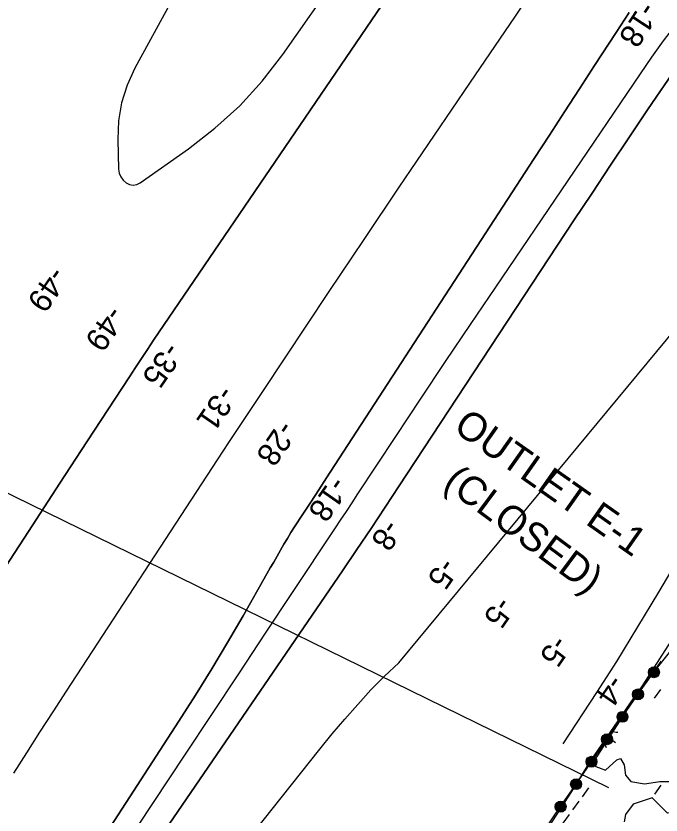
# Model space of a CAD drawing. Extents: x 3905714 to 3926767, y 183354 to 205755.
# Drawn here: x 3915542 to 3916488, y 190163 to 191335 of the extents above; entities that cross this region are included whole.
import ezdxf

# ---------------------------------------------------------------- set-up
doc = ezdxf.new("R2010")
doc.units = 0
for name, color, linetype in [('V-RIVR-EDGE', 7, 'Continuous'), ('V-RIVR-JETY', 7, 'Continuous'), ('V-RIVR-RANG', 7, 'Continuous'), ('V-RRAP-FSHR', 7, 'Continuous'), ('V-TOPO-DPTH', 7, 'Continuous'), ('V-TOPO-MAJR', 7, 'Continuous'), ('V-TOPO-MINR', 7, 'Continuous'), ('V-TOPO-SHOR', 7, 'Continuous'), ('V-UTIL-LINE', 7, 'Continuous'), ('V-WETL-SWMP', 7, 'Continuous')]:
    doc.layers.add(name, color=color, linetype=linetype)

msp = doc.modelspace()

# ---------------------------------------------------------------- linework, layer by layer
at = {"layer": 'V-RIVR-EDGE'}
msp.add_lwpolyline([(3917187.3, 191508.7), (3917014.4, 191257.7), (3916956.7, 191135), (3916863.8, 190988.1), (3916651.8, 190651.5), (3916385.9, 190236.8), (3916406.4, 190229.4), (3916423.1, 190244.3), (3916428.7, 190246.1), (3916434.2, 190236.8), (3916436.1, 190222), (3916443.5, 190212.7), (3916464, 190209), (3916486.3, 190212.7), (3916501.2, 190212.7), (3916512.3, 190207.1), (3916519.8, 190190.4), (3916521.6, 190179.2), (3916512.3, 190168.1), (3916497.5, 190166.2), (3916475.2, 190188.5), (3916447.3, 190179.2), (3916436.1, 190164.3), (3916434.2, 190153.2)], dxfattribs=at)
at = {"layer": 'V-RRAP-FSHR'}
for points in [[(3917284.6, 192007.4), (3917216.4, 191900.2), (3917136.8, 191773.1), (3917049.7, 191632.9), (3916990.5, 191517.4), (3916950.2, 191443.7), (3916837.1, 191198.3), (3916795.1, 191108.3), (3916723.3, 190937), (3916670, 190831.7), (3916645.3, 190765), (3916582.8, 190657.5), (3916484.4, 190490), (3916422.5, 190388.3), (3916393.5, 190343.3), (3916344.2, 190267.8)], [(3916317.9, 190142.8), (3916340.7, 190175.7), (3916363.4, 190208.6), (3916386.1, 190241.5), (3916408.8, 190274.5), (3916431.5, 190307.4), (3916454.2, 190340.3), (3916477.6, 190372.7), (3916502.3, 190404.2), (3916527.1, 190435.7)], [(3916475.1, 190365.9), (3916473.4, 190367.1), (3916471.2, 190369.5), (3916470.5, 190372), (3916470.9, 190375.2), (3916472.5, 190377.4), (3916475.1, 190379.5), (3916478, 190379.6), (3916480.3, 190379.4), (3916482.6, 190377.8), (3916484.1, 190375.7), (3916484.6, 190373.5), (3916484.6, 190371.2), (3916483.6, 190368.8), (3916481, 190366.5), (3916477.9, 190365.6), (3916475.5, 190365.9), (3916473.3, 190368.7), (3916471.7, 190371.2), (3916471.9, 190374), (3916473.3, 190376.9), (3916476, 190378.5), (3916479, 190378.5), (3916481.5, 190377.3), (3916483.3, 190374.8), (3916483.6, 190371.9), (3916482.1, 190368.8), (3916479.4, 190367.1), (3916476.6, 190366.8), (3916473.9, 190368.8), (3916472.8, 190371.3), (3916472.9, 190374.2), (3916474.4, 190376.5), (3916476.8, 190377.7), (3916479.5, 190377.5), (3916481.8, 190375.3), (3916482.6, 190372.6), (3916481, 190369.1), (3916478.4, 190367.8), (3916476.5, 190368), (3916474.5, 190370.2), (3916473.6, 190373), (3916474.5, 190375.3), (3916477.1, 190376.8), (3916479.4, 190376.3), (3916481.5, 190374), (3916481.3, 190371.6), (3916479.9, 190369.6), (3916478, 190368.6), (3916476.1, 190369.3), (3916475.1, 190371.1), (3916474.7, 190373.4), (3916475.9, 190375.1), (3916477.7, 190375.7), (3916479.7, 190374.9), (3916480.5, 190373.2), (3916480.2, 190371.4), (3916478.6, 190369.9), (3916477.3, 190369.9), (3916476.1, 190371.5), (3916475.8, 190373.4), (3916476.7, 190374.5), (3916478.2, 190374.5), (3916479.6, 190373.3), (3916479.3, 190371.7), (3916478.2, 190370.9), (3916476.9, 190371.8), (3916476.8, 190373.5), (3916478, 190373.6), (3916478.6, 190372.6), (3916478.2, 190371.9), (3916477.6, 190372.7)], [(3916452.1, 190333.3), (3916450.3, 190334.4), (3916448, 190336.7), (3916447.1, 190339.1), (3916447.4, 190342.3), (3916448.8, 190344.7), (3916451.3, 190346.9), (3916454.2, 190347.2), (3916456.4, 190347.2), (3916458.8, 190345.7), (3916460.4, 190343.7), (3916461.2, 190341.5), (3916461.2, 190339.3), (3916460.4, 190336.8), (3916457.9, 190334.3), (3916454.9, 190333.3), (3916452.5, 190333.4), (3916450.2, 190336), (3916448.4, 190338.4), (3916448.4, 190341.2), (3916449.6, 190344.2), (3916452.2, 190345.9), (3916455.2, 190346.2), (3916457.8, 190345.2), (3916459.7, 190342.8), (3916460.2, 190339.8), (3916458.9, 190336.6), (3916456.3, 190334.8), (3916453.6, 190334.3), (3916450.8, 190336.2), (3916449.5, 190338.6), (3916449.4, 190341.5), (3916450.8, 190343.9), (3916453.1, 190345.2), (3916455.8, 190345.2), (3916458.3, 190343.2), (3916459.2, 190340.5), (3916457.8, 190336.9), (3916455.3, 190335.4), (3916453.4, 190335.5), (3916451.2, 190337.6), (3916450.2, 190340.3), (3916451, 190342.7), (3916453.5, 190344.4), (3916455.8, 190344), (3916458, 190341.8), (3916458, 190339.4), (3916456.7, 190337.4), (3916454.8, 190336.3), (3916452.9, 190336.8), (3916451.8, 190338.5), (3916451.2, 190340.8), (3916452.3, 190342.5), (3916454.1, 190343.3), (3916456.2, 190342.6), (3916457.1, 190340.9), (3916456.9, 190339.2), (3916455.4, 190337.6), (3916454.1, 190337.4), (3916452.8, 190339), (3916452.4, 190340.8), (3916453.1, 190342), (3916454.7, 190342.1), (3916456.2, 190341), (3916456, 190339.4), (3916454.9, 190338.5), (3916453.5, 190339.4), (3916453.4, 190341), (3916454.5, 190341.2), (3916455.2, 190340.3), (3916454.9, 190339.5), (3916454.2, 190340.3)], [(3916429.4, 190300.4), (3916427.6, 190301.5), (3916425.3, 190303.8), (3916424.4, 190306.2), (3916424.7, 190309.4), (3916426.1, 190311.8), (3916428.6, 190314), (3916431.5, 190314.2), (3916433.7, 190314.2), (3916436.1, 190312.7), (3916437.7, 190310.8), (3916438.5, 190308.6), (3916438.5, 190306.3), (3916437.7, 190303.9), (3916435.2, 190301.4), (3916432.2, 190300.3), (3916429.8, 190300.5), (3916427.5, 190303.1), (3916425.7, 190305.5), (3916425.7, 190308.3), (3916426.9, 190311.2), (3916429.5, 190313), (3916432.5, 190313.2), (3916435.1, 190312.2), (3916437, 190309.8), (3916437.5, 190306.9), (3916436.2, 190303.7), (3916433.6, 190301.9), (3916430.9, 190301.4), (3916428.1, 190303.2), (3916426.8, 190305.7), (3916426.7, 190308.6), (3916428.1, 190311), (3916430.4, 190312.3), (3916433.1, 190312.2), (3916435.6, 190310.2), (3916436.5, 190307.6), (3916435.1, 190303.9), (3916432.6, 190302.5), (3916430.7, 190302.6), (3916428.5, 190304.7), (3916427.5, 190307.4), (3916428.3, 190309.7), (3916430.8, 190311.4), (3916433.1, 190311.1), (3916435.3, 190308.9), (3916435.2, 190306.5), (3916434, 190304.4), (3916432.1, 190303.3), (3916430.2, 190303.9), (3916429.1, 190305.6), (3916428.5, 190307.8), (3916429.6, 190309.6), (3916431.4, 190310.4), (3916433.5, 190309.7), (3916434.4, 190308), (3916434.2, 190306.2), (3916432.7, 190304.6), (3916431.3, 190304.5), (3916430.1, 190306), (3916429.6, 190307.9), (3916430.4, 190309.1), (3916432, 190309.2), (3916433.5, 190308.1), (3916433.3, 190306.5), (3916432.2, 190305.6), (3916430.8, 190306.4), (3916430.7, 190308.1), (3916431.8, 190308.3), (3916432.4, 190307.3), (3916432.1, 190306.5), (3916431.5, 190307.4)], [(3916406.7, 190267.5), (3916404.9, 190268.5), (3916402.6, 190270.8), (3916401.7, 190273.3), (3916402, 190276.5), (3916403.3, 190278.8), (3916405.9, 190281), (3916408.7, 190281.3), (3916411, 190281.3), (3916413.4, 190279.8), (3916415, 190277.9), (3916415.8, 190275.6), (3916415.8, 190273.4), (3916415, 190270.9), (3916412.5, 190268.5), (3916409.5, 190267.4), (3916407.1, 190267.5), (3916404.8, 190270.1), (3916403, 190272.5), (3916403, 190275.3), (3916404.2, 190278.3), (3916406.8, 190280.1), (3916409.8, 190280.3), (3916412.4, 190279.3), (3916414.3, 190276.9), (3916414.8, 190273.9), (3916413.5, 190270.8), (3916410.9, 190269), (3916408.2, 190268.5), (3916405.4, 190270.3), (3916404.1, 190272.8), (3916404, 190275.6), (3916405.3, 190278), (3916407.7, 190279.3), (3916410.4, 190279.3), (3916412.8, 190277.3), (3916413.8, 190274.6), (3916412.4, 190271), (3916409.9, 190269.6), (3916408, 190269.6), (3916405.8, 190271.8), (3916404.8, 190274.5), (3916405.6, 190276.8), (3916408.1, 190278.5), (3916410.4, 190278.1), (3916412.6, 190276), (3916412.5, 190273.6), (3916411.3, 190271.5), (3916409.4, 190270.4), (3916407.4, 190271), (3916406.4, 190272.7), (3916405.8, 190274.9), (3916406.9, 190276.7), (3916408.7, 190277.5), (3916410.8, 190276.8), (3916411.7, 190275.1), (3916411.5, 190273.3), (3916410, 190271.7), (3916408.6, 190271.6), (3916407.3, 190273.1), (3916406.9, 190275), (3916407.7, 190276.2), (3916409.3, 190276.3), (3916410.8, 190275.1), (3916410.6, 190273.5), (3916409.5, 190272.7), (3916408.1, 190273.5), (3916408, 190275.1), (3916409.1, 190275.4), (3916409.7, 190274.4), (3916409.4, 190273.6), (3916408.8, 190274.4)], [(3916384, 190234.5), (3916382.2, 190235.6), (3916379.9, 190237.9), (3916379, 190240.3), (3916379.2, 190243.5), (3916380.6, 190245.9), (3916383.1, 190248.1), (3916386, 190248.4), (3916388.3, 190248.4), (3916390.7, 190246.9), (3916392.3, 190244.9), (3916393.1, 190242.7), (3916393.1, 190240.5), (3916392.3, 190238), (3916389.8, 190235.5), (3916386.8, 190234.5), (3916384.4, 190234.6), (3916382.1, 190237.2), (3916380.3, 190239.6), (3916380.3, 190242.4), (3916381.5, 190245.4), (3916384.1, 190247.1), (3916387.1, 190247.4), (3916389.7, 190246.4), (3916391.6, 190244), (3916392.1, 190241), (3916390.8, 190237.8), (3916388.2, 190236), (3916385.5, 190235.6), (3916382.7, 190237.4), (3916381.4, 190239.9), (3916381.3, 190242.7), (3916382.6, 190245.1), (3916385, 190246.4), (3916387.7, 190246.4), (3916390.1, 190244.4), (3916391.1, 190241.7), (3916389.7, 190238.1), (3916387.2, 190236.6), (3916385.3, 190236.7), (3916383.1, 190238.8), (3916382.1, 190241.5), (3916382.9, 190243.9), (3916385.4, 190245.6), (3916387.7, 190245.2), (3916389.9, 190243.1), (3916389.8, 190240.6), (3916388.6, 190238.6), (3916386.7, 190237.5), (3916384.7, 190238), (3916383.7, 190239.8), (3916383.1, 190242), (3916384.2, 190243.8), (3916386, 190244.5), (3916388.1, 190243.8), (3916389, 190242.1), (3916388.8, 190240.4), (3916387.3, 190238.8), (3916385.9, 190238.6), (3916384.6, 190240.2), (3916384.2, 190242.1), (3916385, 190243.3), (3916386.6, 190243.3), (3916388.1, 190242.2), (3916387.8, 190240.6), (3916386.8, 190239.7), (3916385.4, 190240.6), (3916385.3, 190242.2), (3916386.4, 190242.4), (3916387, 190241.5), (3916386.7, 190240.7), (3916386.1, 190241.5)], [(3916361.3, 190201.6), (3916359.5, 190202.7), (3916357.2, 190205), (3916356.3, 190207.4), (3916356.5, 190210.6), (3916357.9, 190213), (3916360.4, 190215.2), (3916363.3, 190215.5), (3916365.6, 190215.4), (3916368, 190214), (3916369.6, 190212), (3916370.4, 190209.8), (3916370.4, 190207.5), (3916369.6, 190205.1), (3916367.1, 190202.6), (3916364.1, 190201.5), (3916361.7, 190201.7), (3916359.4, 190204.3), (3916357.6, 190206.7), (3916357.6, 190209.5), (3916358.8, 190212.5), (3916361.4, 190214.2), (3916364.4, 190214.4), (3916367, 190213.4), (3916368.9, 190211), (3916369.4, 190208.1), (3916368.1, 190204.9), (3916365.5, 190203.1), (3916362.8, 190202.6), (3916359.9, 190204.5), (3916358.7, 190206.9), (3916358.6, 190209.8), (3916359.9, 190212.2), (3916362.2, 190213.5), (3916365, 190213.4), (3916367.4, 190211.5), (3916368.3, 190208.8), (3916367, 190205.1), (3916364.5, 190203.7), (3916362.6, 190203.8), (3916360.4, 190205.9), (3916359.4, 190208.6), (3916360.1, 190210.9), (3916362.6, 190212.7), (3916365, 190212.3), (3916367.2, 190210.1), (3916367.1, 190207.7), (3916365.9, 190205.6), (3916364, 190204.5), (3916362, 190205.1), (3916361, 190206.8), (3916360.4, 190209), (3916361.5, 190210.8), (3916363.3, 190211.6), (3916365.3, 190210.9), (3916366.2, 190209.2), (3916366.1, 190207.5), (3916364.6, 190205.8), (3916363.2, 190205.7), (3916361.9, 190207.2), (3916361.5, 190209.1), (3916362.3, 190210.3), (3916363.9, 190210.4), (3916365.4, 190209.3), (3916365.1, 190207.7), (3916364.1, 190206.8), (3916362.7, 190207.6), (3916362.6, 190209.3), (3916363.7, 190209.5), (3916364.3, 190208.5), (3916364, 190207.8), (3916363.4, 190208.6)], [(3916338.6, 190168.7), (3916336.8, 190169.7), (3916334.5, 190172), (3916333.6, 190174.5), (3916333.8, 190177.7), (3916335.2, 190180.1), (3916337.7, 190182.2), (3916340.6, 190182.5), (3916342.9, 190182.5), (3916345.3, 190181), (3916346.9, 190179.1), (3916347.6, 190176.8), (3916347.7, 190174.6), (3916346.9, 190172.1), (3916344.4, 190169.7), (3916341.4, 190168.6), (3916339, 190168.7), (3916336.7, 190171.4), (3916334.9, 190173.7), (3916334.9, 190176.5), (3916336.1, 190179.5), (3916338.7, 190181.3), (3916341.7, 190181.5), (3916344.3, 190180.5), (3916346.2, 190178.1), (3916346.7, 190175.2), (3916345.4, 190172), (3916342.8, 190170.2), (3916340.1, 190169.7), (3916337.2, 190171.5), (3916336, 190174), (3916335.9, 190176.8), (3916337.2, 190179.2), (3916339.5, 190180.5), (3916342.3, 190180.5), (3916344.7, 190178.5), (3916345.6, 190175.8), (3916344.2, 190172.2), (3916341.8, 190170.8), (3916339.9, 190170.8), (3916337.7, 190173), (3916336.7, 190175.7), (3916337.4, 190178), (3916339.9, 190179.7), (3916342.3, 190179.4), (3916344.5, 190177.2), (3916344.4, 190174.8), (3916343.2, 190172.7), (3916341.3, 190171.6), (3916339.3, 190172.2), (3916338.3, 190173.9), (3916337.7, 190176.1), (3916338.8, 190177.9), (3916340.6, 190178.7), (3916342.6, 190178), (3916343.5, 190176.3), (3916343.4, 190174.5), (3916341.8, 190172.9), (3916340.5, 190172.8), (3916339.2, 190174.3), (3916338.8, 190176.2), (3916339.6, 190177.4), (3916341.2, 190177.5), (3916342.7, 190176.4), (3916342.4, 190174.7), (3916341.4, 190173.9), (3916340, 190174.7), (3916339.8, 190176.3), (3916341, 190176.6), (3916341.6, 190175.6), (3916341.3, 190174.8), (3916340.7, 190175.6)]]:
    msp.add_lwpolyline(points, dxfattribs=at)
for centre in [(3916477.6, 190372.7), (3916454.2, 190340.3), (3916431.5, 190307.4), (3916408.8, 190274.5), (3916386.1, 190241.5), (3916363.4, 190208.6), (3916340.7, 190175.7)]:
    msp.add_circle(centre, 8, dxfattribs=at)
at = {"layer": 'V-TOPO-DPTH'}
for points in [[(3916593.7, 192145.5), (3916213.5, 191553.1), (3916206.3, 191541.8), (3916199, 191530.5), (3916191.8, 191519.3), (3916184.5, 191508.1), (3916177.2, 191496.9), (3916169.8, 191485.7), (3916162.4, 191474.6), (3916154.9, 191463.5), (3916154.2, 191462.4), (3916146.3, 191450.8), (3916138.5, 191439.2), (3916130.6, 191427.6), (3916122.7, 191416), (3915744.1, 190859.5), (3915735.1, 190846.2), (3915726.2, 190832.9), (3915717.3, 190819.5), (3915708.5, 190806.1), (3915646.4, 190710.8), (3915606.5, 190649.8), (3915566.8, 190588.7), (3915527, 190527.5)], [(3916593.7, 192145.5), (3916213.5, 191553.1), (3916206.3, 191541.8), (3916199, 191530.5), (3916191.8, 191519.3), (3916184.5, 191508.1), (3916177.2, 191496.9), (3916169.8, 191485.7), (3916162.4, 191474.6), (3916154.9, 191463.5), (3916154.2, 191462.4), (3916146.3, 191450.8), (3916138.5, 191439.2), (3916130.6, 191427.6), (3916122.7, 191416), (3915744.1, 190859.5), (3915735.1, 190846.2), (3915726.2, 190832.9), (3915717.3, 190819.5), (3915708.5, 190806.1), (3915646.4, 190710.8), (3915606.5, 190649.8), (3915566.8, 190588.7), (3915527, 190527.5)], [(3917069.2, 191838.9), (3917052.8, 191814.6), (3917034.7, 191791.4), (3916628.8, 191406.9), (3916610.8, 191387.4), (3916593.6, 191367.1), (3916535.8, 191294.1), (3916529.6, 191286), (3916523.4, 191277.8), (3916517.5, 191269.6), (3916511.7, 191261.2), (3916468.4, 191197.2), (3916441, 191156.6), (3916413.8, 191116.1), (3916386.8, 191075.4), (3916359.9, 191034.6), (3916104.1, 190646), (3916083.5, 190614.8), (3916062.8, 190583.7), (3916041.9, 190552.7), (3916020.9, 190521.7), (3915766.9, 190149.8)], [(3915539.3, 190224.6), (3915558.3, 190254.8), (3915577.4, 190284.9), (3915596.8, 190314.9), (3915616.2, 190344.9), (3915837.8, 190684.3), (3915854.3, 190709.5), (3915870.8, 190734.6), (3915887.4, 190759.6), (3915904, 190784.6), (3916001.6, 190930.9), (3916052.9, 191007.5), (3916104.3, 191084), (3916155.9, 191160.4), (3916207.6, 191236.6), (3916274.5, 191334.9), (3916292.8, 191362.1)], [(3915539.3, 190224.6), (3915558.3, 190254.8), (3915577.4, 190284.9), (3915596.8, 190314.9), (3915616.2, 190344.9), (3915837.8, 190684.3), (3915854.3, 190709.5), (3915870.8, 190734.6), (3915887.4, 190759.6), (3915904, 190784.6), (3916001.6, 190930.9), (3916052.9, 191007.5), (3916104.3, 191084), (3916155.9, 191160.4), (3916207.6, 191236.6), (3916274.5, 191334.9), (3916292.8, 191362.1)], [(3915564.7, 189966.9), (3915781, 190301), (3915805.3, 190339.2), (3915829.2, 190377.7), (3915852.4, 190416.6), (3915875.2, 190455.7), (3915910.2, 190517), (3915915.1, 190525.7), (3915920.1, 190534.4), (3915925.1, 190543), (3915930, 190551.7), (3915935, 190560.4), (3915940.2, 190569), (3915945.5, 190577.5), (3915950.8, 190585.9), (3915963, 190604.6), (3915974.6, 190622.4), (3915986.1, 190640.1), (3915997.7, 190657.9), (3916009.2, 190675.7), (3916302.2, 191126.1), (3916324.3, 191160.2), (3916346.5, 191194.3), (3916368.6, 191228.3), (3916390.7, 191262.4), (3916422.3, 191311), (3916428.6, 191320.8), (3916435, 191330.5), (3916441.4, 191340.3)], [(3916441.4, 191340.3), (3916435, 191330.5), (3916428.6, 191320.8), (3916422.3, 191311), (3916390.7, 191262.4), (3916368.6, 191228.3), (3916346.5, 191194.3), (3916324.3, 191160.2), (3916302.2, 191126.1), (3916009.2, 190675.7), (3915997.7, 190657.9), (3915986.1, 190640.1), (3915974.6, 190622.4), (3915963, 190604.6), (3915950.8, 190585.9), (3915945.5, 190577.5), (3915940.2, 190569), (3915935, 190560.4), (3915930, 190551.7), (3915925.1, 190543), (3915920.1, 190534.4), (3915915.1, 190525.7), (3915910.2, 190517), (3915875.2, 190455.7), (3915852.4, 190416.6), (3915829.2, 190377.7), (3915805.3, 190339.2), (3915781, 190301), (3915564.7, 189966.9)]]:
    msp.add_lwpolyline(points, dxfattribs=at)
at = {"layer": 'V-TOPO-MAJR'}
msp.add_lwpolyline([(3915910.4, 191613.9), (3915716.5, 191258.7), (3915705.3, 191233.6), (3915697, 191207.9), (3915692.8, 191181.1), (3915691.4, 191153.7), (3915692.8, 191110.6), (3915693.8, 191104.6), (3915695.8, 191099.2), (3915699.3, 191094.5), (3915703.7, 191090.4), (3915708.9, 191088), (3915714.1, 191087), (3915719.4, 191088), (3915724.6, 191090.4), (3915795.3, 191140.1), (3915834, 191170.5), (3915870.3, 191203.3), (3915903, 191239.7), (3915933.3, 191278.5), (3916096.8, 191511.9)], dxfattribs=at)
at = {"layer": 'V-TOPO-MINR'}
for points in [[(3915527, 190527.5), (3915566.8, 190588.7), (3915606.5, 190649.8), (3915646.4, 190710.8), (3915708.5, 190806.1), (3915717.3, 190819.5), (3915726.2, 190832.9), (3915735.1, 190846.2), (3915744.1, 190859.5), (3916122.7, 191416), (3916130.6, 191427.6), (3916138.5, 191439.2), (3916146.3, 191450.8), (3916154.2, 191462.4), (3916154.9, 191463.5), (3916162.4, 191474.6), (3916169.8, 191485.7), (3916177.2, 191496.9), (3916184.5, 191508.1), (3916191.8, 191519.3), (3916199, 191530.5), (3916206.3, 191541.8), (3916213.5, 191553.1), (3916593.7, 192145.5)], [(3915863.1, 190103.1), (3915987.7, 190260.1), (3916005.8, 190282.3), (3916024.3, 190304.2), (3916043.3, 190325.6), (3916062.6, 190346.8), (3916082.8, 190367.1), (3916103.6, 190386.8), (3916831.8, 191265.2), (3916892, 191320.9), (3916949.8, 191378.8), (3917003.9, 191440.2), (3917055.6, 191503.9), (3917199.9, 191693.5), (3917213.5, 191712.3), (3917316.3, 192136.3)], [(3915766.9, 190149.8), (3916020.9, 190521.7), (3916041.9, 190552.7), (3916062.8, 190583.7), (3916083.5, 190614.8), (3916104.1, 190646), (3916359.9, 191034.6), (3916386.8, 191075.4), (3916413.8, 191116.1), (3916441, 191156.6), (3916468.4, 191197.2), (3916511.7, 191261.2), (3916517.5, 191269.6), (3916523.4, 191277.8), (3916529.6, 191286), (3916535.8, 191294.1), (3916593.6, 191367.1), (3916610.8, 191387.4), (3916628.8, 191406.9), (3917034.7, 191791.4), (3917052.8, 191814.6), (3917069.2, 191838.9)], [(3915539.3, 190224.6), (3915558.3, 190254.8), (3915577.4, 190284.9), (3915596.8, 190314.9), (3915616.2, 190344.9), (3915837.8, 190684.3), (3915854.3, 190709.5), (3915870.8, 190734.6), (3915887.4, 190759.6), (3915904, 190784.6), (3916001.6, 190930.9), (3916052.9, 191007.5), (3916104.3, 191084), (3916155.9, 191160.4), (3916207.6, 191236.6), (3916274.5, 191334.9), (3916292.8, 191362.1)], [(3915564.7, 189966.9), (3915781, 190301), (3915805.3, 190339.2), (3915829.2, 190377.7), (3915852.4, 190416.6), (3915875.2, 190455.7), (3915910.2, 190517), (3915915.1, 190525.7), (3915920.1, 190534.4), (3915925.1, 190543), (3915930, 190551.7), (3915935, 190560.4), (3915940.2, 190569), (3915945.5, 190577.5), (3915950.8, 190585.9), (3915963, 190604.6), (3915974.6, 190622.4), (3915986.1, 190640.1), (3915997.7, 190657.9), (3916009.2, 190675.7), (3916302.2, 191126.1), (3916324.3, 191160.2), (3916346.5, 191194.3), (3916368.6, 191228.3), (3916390.7, 191262.4), (3916422.3, 191311), (3916428.6, 191320.8), (3916435, 191330.5), (3916441.4, 191340.3)], [(3915607.3, 189975.2), (3915790.1, 190251.4), (3915829.5, 190311), (3915868.9, 190370.5), (3915908.3, 190430), (3915947.8, 190489.6), (3916009.8, 190583), (3916018.2, 190595.8), (3916026.7, 190608.6), (3916035.1, 190621.4), (3916043.6, 190634.2), (3916099.2, 190718.5), (3916135.6, 190773.4), (3916172.1, 190828.2), (3916208.8, 190882.9), (3916245.6, 190937.5), (3916457.8, 191250.4), (3916474.6, 191274.6), (3916491.8, 191298.5), (3916509.5, 191322.1), (3916527.5, 191345.3)]]:
    msp.add_lwpolyline(points, dxfattribs=at)
at = {"layer": 'V-TOPO-SHOR'}
msp.add_lwpolyline([(3916324.1, 190146.6), (3916357.3, 190198), (3916383.6, 190240.7), (3916408.1, 190276.8), (3916454.1, 190343.5), (3916482.6, 190381), (3916488.2, 190388.9)], dxfattribs=at)
at = {"layer": 'V-UTIL-LINE'}
msp.add_line((3914355, 191211.2), (3916411.1, 190203.8), dxfattribs=at)
at = {"layer": 'V-WETL-SWMP'}
for p, q in [((3916454.1, 190343.5), (3916482.6, 190381)), ((3916482.6, 190381), (3916488.2, 190388.9)), ((3916487.4, 190347.5), (3916478, 190334.6)), ((3916408.1, 190276.8), (3916454.1, 190343.5)), ((3916383.6, 190240.7), (3916408.1, 190276.8)), ((3916409.4, 190278.6), (3916421.4, 190269.8)), ((3916357.3, 190198), (3916383.6, 190240.7)), ((3916487.8, 190207.1), (3916478.4, 190194.2)), ((3916324.1, 190146.6), (3916357.3, 190198)), ((3916381.7, 190203.1), (3916372.2, 190190.2)), ((3916367.5, 190183.7), (3916358, 190170.8)), ((3916353.3, 190164.4), (3916343.8, 190151.5))]:
    msp.add_line(p, q, dxfattribs=at)
for centre, start, end in [((3916423.4, 190302.6), 242.1482, 274.5436), ((3916390.7, 190258), 13, 43.2555)]:
    msp.add_arc(centre, 17.6, start, end, dxfattribs=at)

# ---------------------------------------------------------------- texts
at = {"layer": 'V-RIVR-JETY'}
for s, rotation, p in [('OUTLET E-1', 324.8803, (3916181.7, 190727.5)), ('(CLOSED)', 323.3644, (3916166.9, 190646))]:
    msp.add_text(s, height=42, rotation=rotation, dxfattribs=at).set_placement(p)
at = {"layer": 'V-RIVR-RANG'}
for s, rotation, p in [('-18', 236.6583, (3916460.4, 191358.1)), ('-49', 235.3801, (3915594.3, 190969.9)), ('-49', 235.3801, (3915678.8, 190912.4)), ('-35', 235.3801, (3915762.5, 190858.9)), ('-31', 235.3801, (3915842.1, 190795.3)), ('-28', 235.3801, (3915929.9, 190744.1)), ('-18', 235.2383, (3916006.3, 190662.3)), ('-8', 235.2383, (3916084.2, 190599.2)), ('-5', 235.2383, (3916166.8, 190542.8)), ('-5', 235.2383, (3916249.1, 190486)), ('-5', 235.2383, (3916331.4, 190429.2)), ('-4', 235.2383, (3916413.2, 190371.6))]:
    msp.add_text(s, height=33.5, rotation=rotation, dxfattribs=at).set_placement(p)

doc.saveas('drawing.dxf')
